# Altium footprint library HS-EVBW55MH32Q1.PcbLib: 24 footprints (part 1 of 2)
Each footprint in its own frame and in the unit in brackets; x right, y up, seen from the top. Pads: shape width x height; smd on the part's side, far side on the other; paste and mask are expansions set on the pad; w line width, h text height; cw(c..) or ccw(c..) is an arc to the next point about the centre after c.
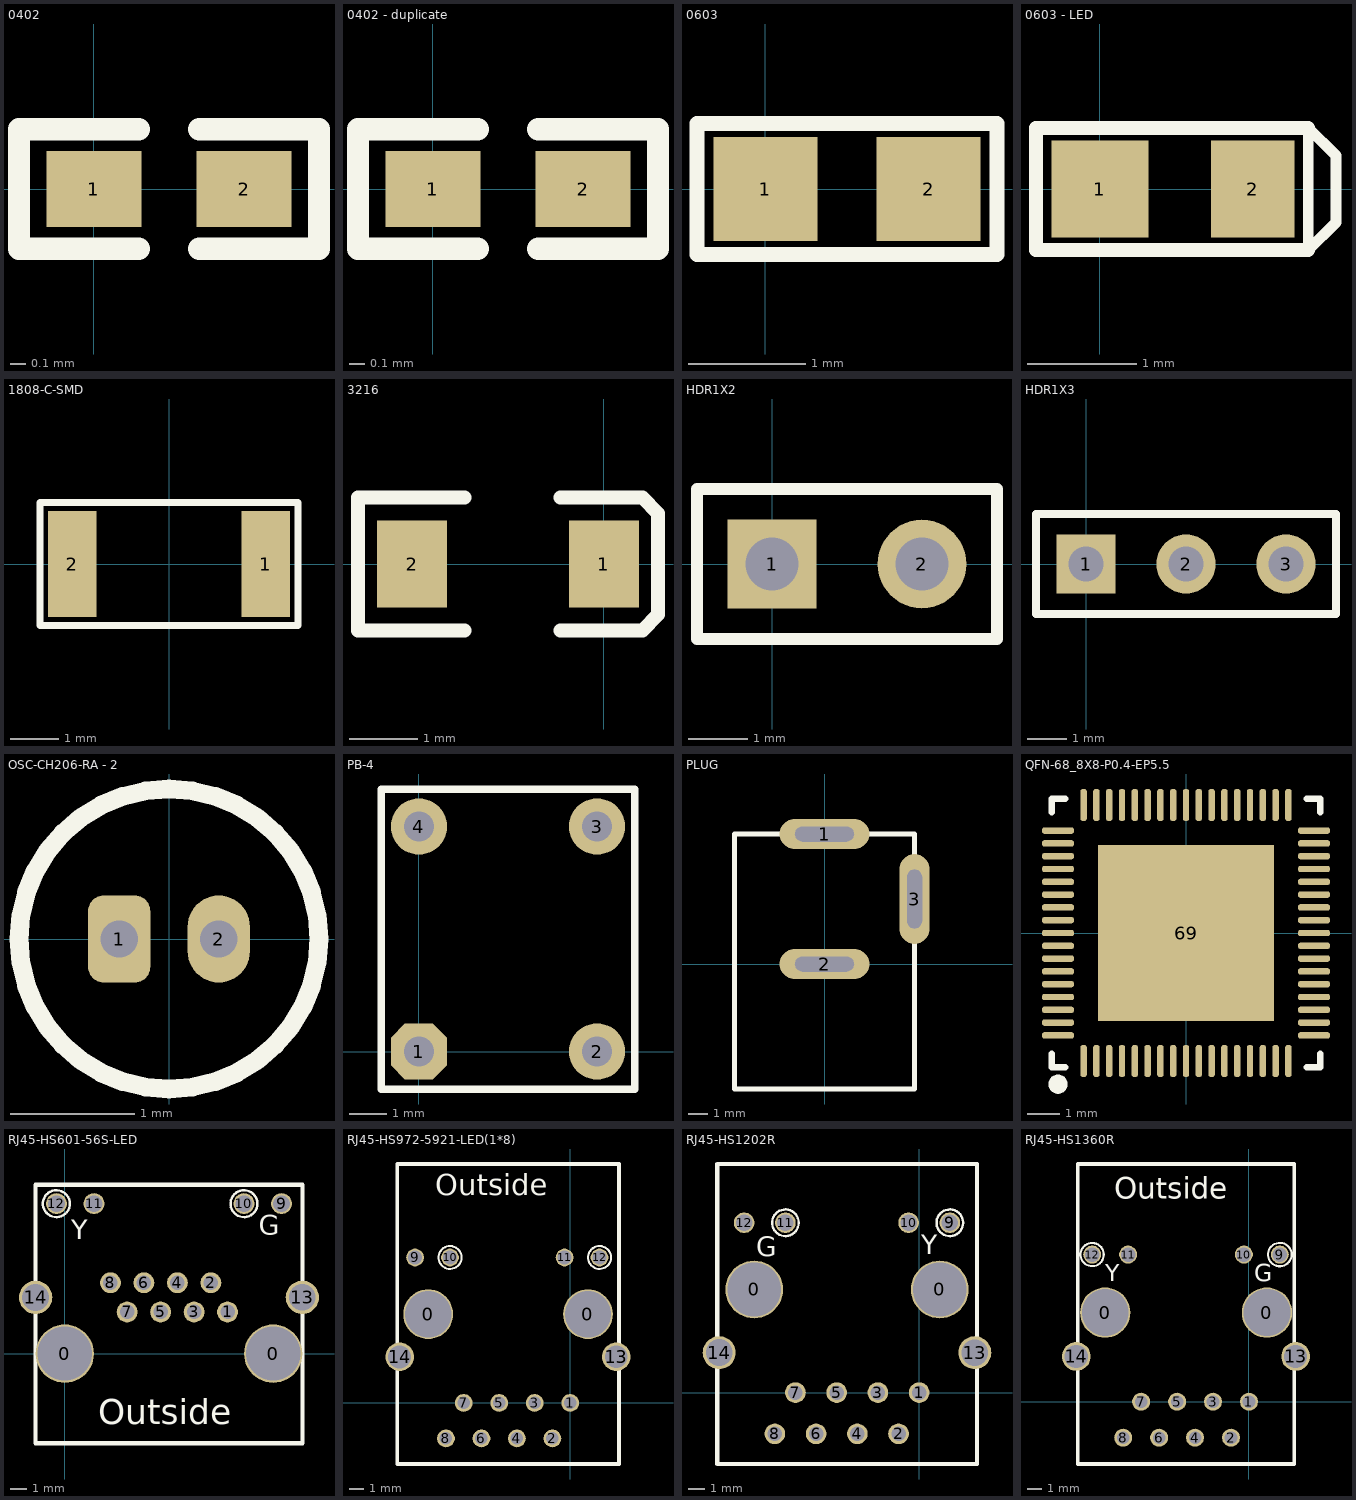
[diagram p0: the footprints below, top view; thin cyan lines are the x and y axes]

## 0402 [mil]
height 43.31
pads (2):
  rect 25x20 smd: 1(0,0) 2(39.37,0)
Top Overlay:
  lines w5.91: 11.81,-15.75 -19.68,-15.75 -19.68,15.75 11.81,15.75 ; 27.56,-15.75 59.06,-15.75 59.06,15.75 27.56,15.75

## 0402 - duplicate [mil]
height 43.31
pads (2):
  rect 25x20 smd: 1(0,0) 2(39.37,0)
Top Overlay:
  lines w5.91: 11.81,-15.75 -19.68,-15.75 -19.68,15.75 11.81,15.75 ; 27.56,-15.75 59.06,-15.75 59.06,15.75 27.56,15.75

## 0603 [mil]
height 43.31
pads (2):
  rect 35x35 smd: 1(0,0) 2(55,0)
Top Overlay:
  lines w5: -23,-22 -23,22 78,22 78,-22 -23,-22

## 0603 - LED [mil]
height 43.31
pads (2):
  rect 35x35 smd: 1(0,0)
  rect 30x35 smd: 2(55,0)
Top Overlay:
  lines w3.94: 75,-22 75,22 85,12 85,-12 75,-22
  lines w5: 75,-22 -23,-22 -23,22 75,22

## 1808-C-SMD [mm] "1808-C-SMD"
pads (2):
  rect 1x2.2 smd: 1(2,0) 2(-2,0)
Top Overlay:
  lines w0.152: -2.667,-1.27 -2.667,1.27 2.667,1.27 2.667,-1.27 -2.667,-1.27

## 3216 [mil]
height 43.31
pads (2):
  rect 40x50 smd: 1(0,0) 2(-110,0)
Top Overlay:
  lines w8: -80,-38 -141,-38 -141,38 -80,38 ; -25,-38 22,-38 31,-29 31,29 22,38 -25,38

## HDR1X2 [mm]
height 0.55
pads (2):
  rect 1.5x1.5 hole 0.9: 1(0,0)
  round 1.5 hole 0.9: 2(2.54,0)
Top Overlay:
  lines w0.2: -1.27,-1.27 3.81,-1.27 3.81,1.27 -1.27,1.27 -1.27,-1.27

## HDR1X3 [mm] "Connector; Header; 3 Position"
height 1.1
pads (3):
  rect 1.5x1.5 hole 0.9: 1(0,0)
  round 1.5 hole 0.9: 2(2.54,0) 3(5.08,0)
Top Overlay:
  lines w0.2: -1.27,-1.27 -1.27,1.27 6.35,1.27 6.35,-1.27 -1.27,-1.27

## OSC-CH206-RA - 2 [mm]
height 3.9
pads (2):
  rrect50% 0.5x0.7 hole 0.3: 1(-0.4,0)
  oval 0.5x0.7 hole 0.3: 2(0.4,0)
Top Overlay:
  circle w0.15: c0,0 r1.205

## PB-4 [mil]
height 21.65
pads (4):
  oct 60x60 hole 32: 1(0,0)
  round 60 hole 32: 2(190,0) 3(190,240) 4(0,240)
Top Overlay:
  lines w8: -40,-40 -40,280 230,280 230,-40 -40,-40

## PLUG [mil]
pads (3):
  oval 180x60 hole 30 slot 118.11 at 0 deg: 1(0,260) 2(0,0)
  oval 60x180 hole 30 slot 118.11 at 90 deg: 3(180,130)
Top Overlay:
  lines w10: -180,-250 180,-250 180,260 -180,260 -180,-250

## QFN-68_8X8-P0.4-EP5.5 [mm]
height 1.45
pads (69):
  rrect80% 0.2x1 smd mask+0.051: 1(-3.2,-4) 2(-2.8,-4) 3(-2.4,-4) 4(-2,-4) 5(-1.6,-4) 6(-1.2,-4) 7(-0.8,-4) 8(-0.4,-4) 9(0,-4) 10(0.4,-4) 11(0.8,-4) 12(1.2,-4) 13(1.6,-4) 14(2,-4) 15(2.4,-4) 16(2.8,-4) 17(3.2,-4) 35(3.2,4) 36(2.8,4) 37(2.4,4) 38(2,4) 39(1.6,4) 40(1.2,4) 41(0.8,4) 42(0.4,4) 43(0,4) 44(-0.4,4) 45(-0.8,4) 46(-1.2,4) 47(-1.6,4) 48(-2,4) 49(-2.4,4) 50(-2.8,4) 51(-3.2,4)
  rrect80% 1x0.2 smd mask+0.051: 18(4,-3.2) 19(4,-2.8) 20(4,-2.4) 21(4,-2) 22(4,-1.6) 23(4,-1.2) 24(4,-0.8) 25(4,-0.4) 26(4,0) 27(4,0.4) 28(4,0.8) 29(4,1.2) 30(4,1.6) 31(4,2) 32(4,2.4) 33(4,2.8) 34(4,3.2) 52(-4,3.2) 53(-4,2.8) 54(-4,2.4) 55(-4,2) 56(-4,1.6) 57(-4,1.2) 58(-4,0.8) 59(-4,0.4) 60(-4,0) 61(-4,-0.4) 62(-4,-0.8) 63(-4,-1.2) 64(-4,-1.6) 65(-4,-2) 66(-4,-2.4) 67(-4,-2.8) 68(-4,-3.2)
  rect 5.5x5.5 smd paste-100 mask+0.051: 69(0,0)
Top Overlay:
  lines w0.2: -4.2,-3.775 -4.2,-4.2 -3.775,-4.2 ; -4.2,3.775 -4.2,4.2 -3.775,4.2 ; 3.775,-4.2 4.2,-4.2 4.2,-3.775 ; 3.775,4.2 4.2,4.2 4.2,3.775
  lines w0.3: -4,-4.575 ccw(c-3.999,-4.725) -3.999,-4.875 ccw(c-3.999,-4.725) -3.998,-4.575
3D body: height 1.05, standoff 0, extent -7.999,-7.999 8.001,8.001

## RJ45-HS601-56S-LED [mil]
height 519.68
pads (16):
  round 140 hole 130: 0(0,0) 0(500,0)
  round 50 hole 35: 1(390.55,100) 2(350.39,170.08) 3(310.24,100) 4(270.08,170.08) 5(229.92,100) 6(189.76,170.08) 7(149.61,100) 8(109.45,170.08)
  round 50 hole 40: 9(520.08,359.84) 10(429.92,359.84) 11(70.08,359.84) 12(-20.08,359.84)
  round 80 hole 64: 13(569.88,135.04)
  round 80 hole 65: 14(-69.88,135.04)
Top Overlay:
  circle w5.91: c429.92,359.84 r32.28
  circle w5.91: c-20.25,359.84 r32.28
  lines w10: -70.08,-214.96 -70.08,405.12 570.08,405.12 570.08,-214.96 -70.08,-214.96
  text "Outside" at 80,-170 h60
  text "G" at 465,285 h47.24
  text "Y" at 15,275 h47.24

## RJ45-HS972-5921-LED(1*8) [mil]
height 537.8
pads (16):
  round 140 hole 130: 0(-400,250) 0(50,250)
  round 50 hole 35: 1(0,0) 2(-50,-100) 3(-100,0) 4(-150,-100) 5(-200,0) 6(-250,-100) 7(-300,0) 8(-350,-100)
  round 50 hole 40: 9(-437.01,409.84) 10(-338.58,409.84) 11(-15.75,409.84) 12(82.68,409.84)
  round 80 hole 64: 13(129.92,129.92)
  round 80 hole 65: 14(-480.31,129.92)
Top Overlay:
  circle w5.91: c-338.58,409.84 r32.28
  circle w5.91: c82.68,409.84 r32.28
  lines w10: -487.6,-172.05 137.6,-172.05 ; -487.6,-171.26 -487.6,673.23 137.6,673.23 137.6,-171.26
  text "Outside" at -380,585 h60

## RJ45-HS1202R [mil]
height 633.46
pads (16):
  round 140 hole 130: 0(-400,250) 0(50,250)
  round 50 hole 35: 1(0,0) 2(-50,-100) 3(-100,0) 4(-150,-100) 5(-200,0) 6(-250,-100) 7(-300,0) 8(-350,-100)
  round 50 hole 40: 9(74.41,411.81) 10(-25.59,411.81) 11(-324.41,411.81) 12(-424.41,411.81)
  round 80 hole 64: 13(135.04,96.85)
  round 80 hole 65: 14(-485.04,96.85)
Top Overlay:
  circle w5.91: c-324.41,411.81 r32.28
  circle w5.91: c74.41,411.81 r32.3
  lines w10: -489.76,-173.23 140.16,-173.23 140.16,554.33 -489.76,554.33 -489.76,-173.23
  text "G" at -395,330 h47.24
  text "Y" at 5,335 h47.24

## RJ45-HS1360R [mil]
height 537.8
pads (16):
  round 140 hole 130: 0(-400,248.03) 0(50,248.03)
  round 50 hole 35: 1(0,0) 2(-50,-100) 3(-100,0) 4(-150,-100) 5(-200,0) 6(-250,-100) 7(-300,0) 8(-350,-100)
  round 50 hole 40: 9(85.83,409.45) 10(-14.17,409.45) 11(-336.22,409.45) 12(-436.22,409.45)
  round 80 hole 64: 13(129.92,125.98)
  round 80 hole 65: 14(-480.31,125.98)
Top Overlay:
  circle w5.91: c-436.22,409.45 r32.28
  circle w5.91: c85.83,409.45 r32.68
  lines w10: -476.38,-173.23 -476.38,661.42 125.98,661.42 125.98,-173.23 -476.38,-173.23
  text "Outside" at -375,565 h60
  text "Y" at -400,335 h47.24
  text "G" at 15,335 h47.24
